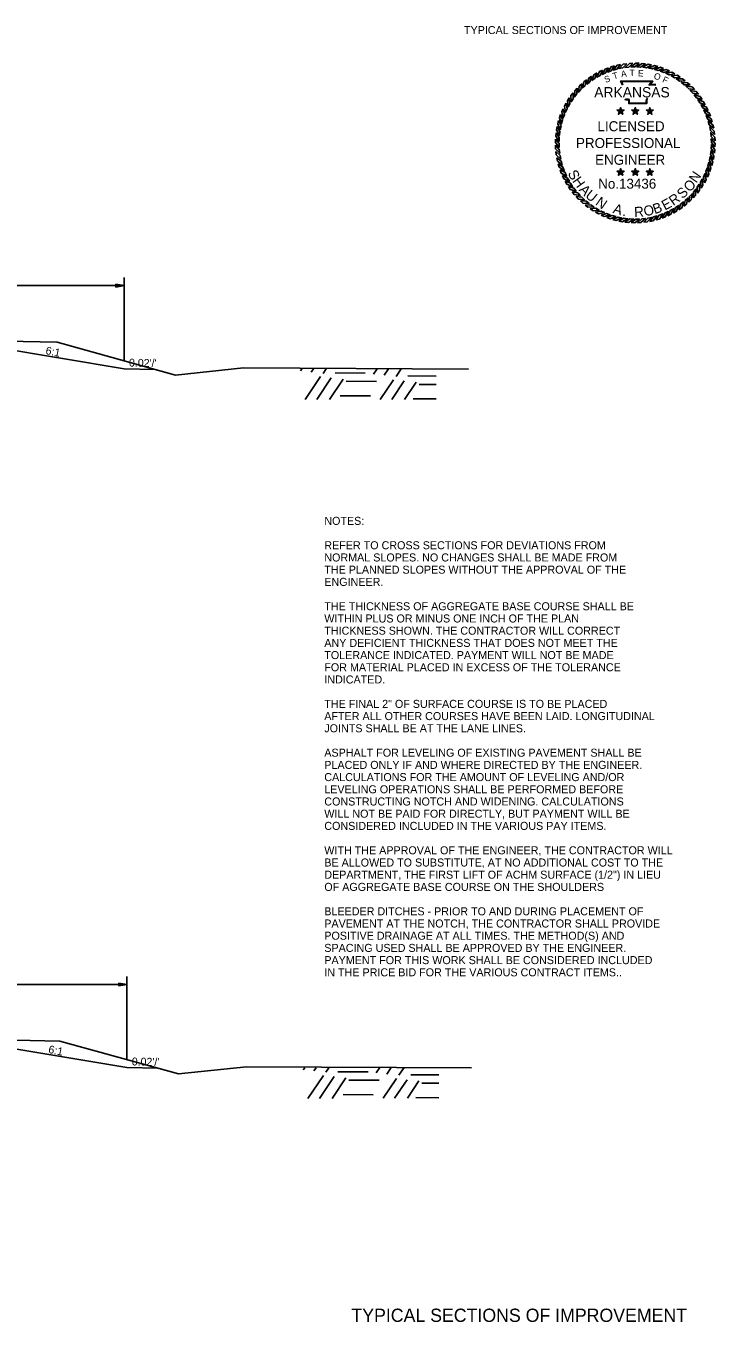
# Model space of a CAD drawing. Extents: x 1398565 to 1398920, y 1968324 to 1968581.
# Drawn here: x 1398668.3 to 1398719.8, y 1968325.3 to 1968422.2 of the extents above; entities that cross this region are included whole.
import ezdxf

# ---------------------------------------------------------------- set-up
doc = ezdxf.new("R2010")
doc.units = 0
for name, color, linetype in [('1', 7, 'Continuous'), ('10', 7, 'Continuous'), ('19', 7, 'Continuous'), ('42', 7, 'Continuous'), ('9', 7, 'Continuous'), ('G-ANNO-SYMB', 7, 'Continuous')]:
    doc.layers.add(name, color=color, linetype=linetype)

msp = doc.modelspace()

# ---------------------------------------------------------------- linework, layer by layer
at = {"layer": '19'}
for p, q in [((1398653.586, 1968402.763), (1398675.586, 1968402.763)), ((1398674.986, 1968402.658), (1398674.986, 1968402.868)), ((1398674.986, 1968402.868), (1398675.586, 1968402.763)), ((1398674.986, 1968402.813), (1398675.426, 1968402.778)), ((1398675.586, 1968402.763), (1398674.986, 1968402.658)), ((1398675.426, 1968402.748), (1398674.986, 1968402.708)), ((1398675.586, 1968397.155), (1398675.586, 1968403.363)), ((1398661.586, 1968398.88), (1398675.586, 1968396.547)), ((1398677.903, 1968396.501), (1398675.586, 1968396.547)), ((1398675.795, 1968344.892), (1398675.795, 1968351.1)), ((1398653.795, 1968350.5), (1398675.795, 1968350.5)), ((1398675.195, 1968350.395), (1398675.195, 1968350.605)), ((1398675.195, 1968350.605), (1398675.795, 1968350.5)), ((1398675.195, 1968350.55), (1398675.635, 1968350.515)), ((1398675.795, 1968350.5), (1398675.195, 1968350.395)), ((1398675.635, 1968350.485), (1398675.195, 1968350.445)), ((1398661.795, 1968346.618), (1398675.795, 1968344.284)), ((1398678.111, 1968344.238), (1398675.795, 1968344.284))]:
    msp.add_line(p, q, dxfattribs=at)
at = {"layer": '42'}
for points in [[(1398653.586, 1968398.994), (1398661.671, 1968398.71), (1398670.586, 1968398.534), (1398679.441, 1968396.073), (1398684.522, 1968396.615), (1398701.339, 1968396.526)], [(1398653.795, 1968346.731), (1398661.88, 1968346.447), (1398670.795, 1968346.271), (1398679.65, 1968343.81), (1398684.731, 1968344.352), (1398701.547, 1968344.263)]]:
    msp.add_lwpolyline(points, dxfattribs=at)
at = {"layer": '9'}
for p, q in [((1398688.776, 1968396.383), (1398688.88, 1968396.537)), ((1398689.125, 1968394.243), (1398690.279, 1968395.959)), ((1398689.574, 1968396.291), (1398689.74, 1968396.538)), ((1398689.985, 1968394.244), (1398691.076, 1968395.867)), ((1398690.464, 1968396.2), (1398690.692, 1968396.54)), ((1398690.938, 1968394.246), (1398691.966, 1968395.776)), ((1398691.354, 1968396.239), (1398693.615, 1968396.224)), ((1398694.227, 1968396.151), (1398694.493, 1968396.547)), ((1398694.739, 1968394.253), (1398695.73, 1968395.727)), ((1398695.025, 1968396.06), (1398695.353, 1968396.548)), ((1398695.915, 1968395.969), (1398696.306, 1968396.55)), ((1398696.805, 1968396.007), (1398698.911, 1968395.994)), ((1398692.189, 1968395.61), (1398694.451, 1968395.595)), ((1398695.599, 1968394.254), (1398696.527, 1968395.636)), ((1398696.551, 1968394.256), (1398697.417, 1968395.545)), ((1398697.64, 1968395.378), (1398698.912, 1968395.37)), ((1398691.746, 1968394.533), (1398694.008, 1968394.519)), ((1398697.197, 1968394.301), (1398698.914, 1968394.29)), ((1398688.985, 1968344.12), (1398689.089, 1968344.274)), ((1398689.334, 1968341.98), (1398690.488, 1968343.696)), ((1398689.782, 1968344.029), (1398689.948, 1968344.276)), ((1398690.194, 1968341.982), (1398691.285, 1968343.605)), ((1398690.673, 1968343.937), (1398690.901, 1968344.277)), ((1398691.146, 1968341.983), (1398692.175, 1968343.513)), ((1398691.562, 1968343.976), (1398693.824, 1968343.961)), ((1398692.398, 1968343.347), (1398694.66, 1968343.332)), ((1398694.436, 1968343.888), (1398694.702, 1968344.284)), ((1398694.948, 1968341.99), (1398695.939, 1968343.464)), ((1398695.234, 1968343.797), (1398695.562, 1968344.285)), ((1398695.807, 1968341.991), (1398696.736, 1968343.373)), ((1398696.124, 1968343.706), (1398696.514, 1968344.287)), ((1398697.014, 1968343.744), (1398699.119, 1968343.731)), ((1398696.76, 1968341.993), (1398697.626, 1968343.282)), ((1398697.849, 1968343.115), (1398699.121, 1968343.107)), ((1398691.955, 1968342.27), (1398694.217, 1968342.256)), ((1398697.406, 1968342.039), (1398699.122, 1968342.028))]:
    msp.add_line(p, q, dxfattribs=at)
at = {"layer": 'G-ANNO-SYMB'}
for points in [[(1398711.784, 1968419.05), (1398711.545, 1968418.958), (1398711.32, 1968418.56), (1398711.572, 1968418.674)], [(1398712.231, 1968419.19), (1398711.985, 1968419.117), (1398711.73, 1968418.738), (1398711.99, 1968418.832)], [(1398712.688, 1968419.294), (1398712.437, 1968419.241), (1398712.152, 1968418.883), (1398712.42, 1968418.957)], [(1398713.152, 1968419.362), (1398712.897, 1968419.329), (1398712.585, 1968418.995), (1398712.857, 1968419.047)], [(1398713.619, 1968419.394), (1398713.363, 1968419.381), (1398713.026, 1968419.072), (1398713.301, 1968419.103)], [(1398714.087, 1968419.389), (1398713.831, 1968419.396), (1398713.471, 1968419.115), (1398713.748, 1968419.124)], [(1398714.554, 1968419.347), (1398714.299, 1968419.375), (1398713.917, 1968419.122), (1398714.194, 1968419.109)], [(1398715.016, 1968419.269), (1398714.764, 1968419.316), (1398714.364, 1968419.095), (1398714.639, 1968419.06)], [(1398715.47, 1968419.155), (1398715.222, 1968419.222), (1398714.806, 1968419.032), (1398715.078, 1968418.976)], [(1398715.914, 1968419.005), (1398715.672, 1968419.092), (1398715.243, 1968418.935), (1398715.509, 1968418.858)], [(1398710.146, 1968418.155), (1398709.946, 1968417.994), (1398709.855, 1968417.546), (1398710.06, 1968417.732)], [(1398710.528, 1968418.426), (1398710.316, 1968418.281), (1398710.19, 1968417.842), (1398710.409, 1968418.012)], [(1398710.93, 1968418.667), (1398710.708, 1968418.539), (1398710.547, 1968418.111), (1398710.779, 1968418.263)], [(1398711.35, 1968418.875), (1398711.118, 1968418.765), (1398710.925, 1968418.351), (1398711.168, 1968418.484)], [(1398716.345, 1968418.822), (1398716.111, 1968418.926), (1398715.67, 1968418.804), (1398715.929, 1968418.706)], [(1398716.76, 1968418.604), (1398716.535, 1968418.727), (1398716.086, 1968418.64), (1398716.337, 1968418.522)], [(1398717.157, 1968418.355), (1398716.942, 1968418.496), (1398716.488, 1968418.444), (1398716.728, 1968418.307)], [(1398717.533, 1968418.076), (1398717.33, 1968418.233), (1398716.873, 1968418.217), (1398717.102, 1968418.061)], [(1398709.144, 1968417.174), (1398708.987, 1968416.971), (1398709.003, 1968416.514), (1398709.159, 1968416.743)], [(1398709.452, 1968417.527), (1398709.28, 1968417.337), (1398709.26, 1968416.88), (1398709.433, 1968417.096)], [(1398709.787, 1968417.855), (1398709.6, 1968417.678), (1398709.545, 1968417.224), (1398709.734, 1968417.427)], [(1398717.886, 1968417.768), (1398717.695, 1968417.94), (1398717.239, 1968417.96), (1398717.455, 1968417.787)], [(1398718.213, 1968417.433), (1398718.037, 1968417.62), (1398717.583, 1968417.675), (1398717.785, 1968417.486)], [(1398718.514, 1968417.074), (1398718.353, 1968417.274), (1398717.905, 1968417.365), (1398718.091, 1968417.16)], [(1398718.785, 1968416.692), (1398718.64, 1968416.904), (1398718.201, 1968417.03), (1398718.371, 1968416.811)], [(1398708.616, 1968416.401), (1398708.493, 1968416.176), (1398708.58, 1968415.727), (1398708.698, 1968415.978)], [(1398708.865, 1968416.798), (1398708.724, 1968416.583), (1398708.776, 1968416.129), (1398708.913, 1968416.37)], [(1398712.698, 1968415.806), (1398712.76, 1968415.891), (1398712.698, 1968416.079), (1398712.637, 1968415.891)], [(1398713.789, 1968415.806), (1398713.851, 1968415.891), (1398713.789, 1968416.079), (1398713.728, 1968415.891)], [(1398714.88, 1968415.806), (1398714.942, 1968415.891), (1398714.88, 1968416.079), (1398714.819, 1968415.891)], [(1398719.026, 1968416.29), (1398718.898, 1968416.512), (1398718.469, 1968416.672), (1398718.622, 1968416.441)], [(1398719.234, 1968415.87), (1398719.124, 1968416.102), (1398718.709, 1968416.295), (1398718.843, 1968416.052)], [(1398708.065, 1968415.111), (1398707.998, 1968414.864), (1398708.188, 1968414.447), (1398708.244, 1968414.719)], [(1398708.215, 1968415.555), (1398708.128, 1968415.314), (1398708.285, 1968414.884), (1398708.362, 1968415.15)], [(1398708.398, 1968415.986), (1398708.294, 1968415.752), (1398708.416, 1968415.311), (1398708.514, 1968415.571)], [(1398712.698, 1968415.806), (1398712.637, 1968415.891), (1398712.439, 1968415.891), (1398712.599, 1968415.774)], [(1398712.698, 1968415.806), (1398712.599, 1968415.774), (1398712.538, 1968415.586), (1398712.698, 1968415.702)], [(1398712.698, 1968415.806), (1398712.798, 1968415.774), (1398712.958, 1968415.891), (1398712.76, 1968415.891)], [(1398712.698, 1968415.806), (1398712.698, 1968415.702), (1398712.859, 1968415.586), (1398712.798, 1968415.774)], [(1398713.789, 1968415.806), (1398713.728, 1968415.891), (1398713.53, 1968415.891), (1398713.69, 1968415.774)], [(1398713.789, 1968415.806), (1398713.69, 1968415.774), (1398713.629, 1968415.586), (1398713.789, 1968415.702)], [(1398713.789, 1968415.806), (1398713.888, 1968415.774), (1398714.049, 1968415.891), (1398713.851, 1968415.891)], [(1398713.789, 1968415.806), (1398713.789, 1968415.702), (1398713.95, 1968415.586), (1398713.888, 1968415.774)], [(1398714.88, 1968415.806), (1398714.819, 1968415.891), (1398714.621, 1968415.891), (1398714.781, 1968415.774)], [(1398714.88, 1968415.806), (1398714.781, 1968415.774), (1398714.72, 1968415.586), (1398714.88, 1968415.702)], [(1398714.88, 1968415.806), (1398714.979, 1968415.774), (1398715.14, 1968415.891), (1398714.942, 1968415.891)], [(1398714.88, 1968415.806), (1398714.88, 1968415.702), (1398715.041, 1968415.586), (1398714.979, 1968415.774)], [(1398719.408, 1968415.436), (1398719.317, 1968415.675), (1398718.919, 1968415.9), (1398719.033, 1968415.648)], [(1398719.548, 1968414.989), (1398719.476, 1968415.235), (1398719.097, 1968415.49), (1398719.191, 1968415.23)], [(1398707.873, 1968414.195), (1398707.845, 1968413.94), (1398708.098, 1968413.559), (1398708.111, 1968413.836)], [(1398707.951, 1968414.657), (1398707.904, 1968414.405), (1398708.125, 1968414.005), (1398708.16, 1968414.28)], [(1398719.653, 1968414.532), (1398719.6, 1968414.783), (1398719.242, 1968415.068), (1398719.315, 1968414.8)], [(1398719.721, 1968414.068), (1398719.688, 1968414.323), (1398719.354, 1968414.635), (1398719.406, 1968414.362)], [(1398719.753, 1968413.601), (1398719.74, 1968413.857), (1398719.431, 1968414.194), (1398719.462, 1968413.919)], [(1398707.831, 1968413.728), (1398707.824, 1968413.472), (1398708.105, 1968413.112), (1398708.096, 1968413.389)], [(1398707.826, 1968413.26), (1398707.839, 1968413.004), (1398708.148, 1968412.667), (1398708.117, 1968412.942)], [(1398719.706, 1968412.666), (1398719.734, 1968412.921), (1398719.481, 1968413.302), (1398719.468, 1968413.026)], [(1398719.748, 1968413.133), (1398719.755, 1968413.389), (1398719.474, 1968413.749), (1398719.482, 1968413.472)], [(1398707.858, 1968412.793), (1398707.891, 1968412.538), (1398708.225, 1968412.226), (1398708.173, 1968412.499)], [(1398707.926, 1968412.329), (1398707.979, 1968412.078), (1398708.337, 1968411.794), (1398708.263, 1968412.061)], [(1398719.514, 1968411.75), (1398719.581, 1968411.998), (1398719.391, 1968412.414), (1398719.335, 1968412.142)], [(1398719.628, 1968412.204), (1398719.675, 1968412.456), (1398719.454, 1968412.856), (1398719.419, 1968412.581)], [(1398708.03, 1968411.873), (1398708.103, 1968411.626), (1398708.482, 1968411.371), (1398708.388, 1968411.632)], [(1398708.17, 1968411.426), (1398708.262, 1968411.186), (1398708.66, 1968410.961), (1398708.546, 1968411.213)], [(1398712.698, 1968411.238), (1398712.637, 1968411.322), (1398712.439, 1968411.322), (1398712.599, 1968411.206)], [(1398712.698, 1968411.238), (1398712.599, 1968411.206), (1398712.538, 1968411.017), (1398712.698, 1968411.134)], [(1398712.698, 1968411.238), (1398712.76, 1968411.322), (1398712.698, 1968411.511), (1398712.637, 1968411.322)], [(1398712.698, 1968411.238), (1398712.798, 1968411.206), (1398712.958, 1968411.322), (1398712.76, 1968411.322)], [(1398712.698, 1968411.238), (1398712.698, 1968411.134), (1398712.859, 1968411.017), (1398712.798, 1968411.206)], [(1398713.789, 1968411.238), (1398713.728, 1968411.322), (1398713.53, 1968411.322), (1398713.69, 1968411.206)], [(1398713.789, 1968411.238), (1398713.69, 1968411.206), (1398713.629, 1968411.017), (1398713.789, 1968411.134)], [(1398713.789, 1968411.238), (1398713.851, 1968411.322), (1398713.789, 1968411.511), (1398713.728, 1968411.322)], [(1398713.789, 1968411.238), (1398713.888, 1968411.206), (1398714.049, 1968411.322), (1398713.851, 1968411.322)], [(1398713.789, 1968411.238), (1398713.789, 1968411.134), (1398713.95, 1968411.017), (1398713.888, 1968411.206)], [(1398714.88, 1968411.238), (1398714.819, 1968411.322), (1398714.621, 1968411.322), (1398714.781, 1968411.206)], [(1398714.88, 1968411.238), (1398714.781, 1968411.206), (1398714.72, 1968411.017), (1398714.88, 1968411.134)], [(1398714.88, 1968411.238), (1398714.942, 1968411.322), (1398714.88, 1968411.511), (1398714.819, 1968411.322)], [(1398714.88, 1968411.238), (1398714.979, 1968411.206), (1398715.14, 1968411.322), (1398714.942, 1968411.322)], [(1398714.88, 1968411.238), (1398714.88, 1968411.134), (1398715.041, 1968411.017), (1398714.979, 1968411.206)], [(1398719.18, 1968410.875), (1398719.285, 1968411.109), (1398719.163, 1968411.55), (1398719.065, 1968411.291)], [(1398719.364, 1968411.306), (1398719.45, 1968411.548), (1398719.294, 1968411.977), (1398719.217, 1968411.711)], [(1398708.345, 1968410.991), (1398708.455, 1968410.759), (1398708.869, 1968410.566), (1398708.736, 1968410.809)], [(1398708.553, 1968410.571), (1398708.681, 1968410.349), (1398709.109, 1968410.189), (1398708.957, 1968410.42)], [(1398718.435, 1968409.687), (1398718.591, 1968409.89), (1398718.576, 1968410.347), (1398718.42, 1968410.118)], [(1398718.714, 1968410.063), (1398718.854, 1968410.278), (1398718.803, 1968410.732), (1398718.665, 1968410.492)], [(1398718.963, 1968410.46), (1398719.086, 1968410.685), (1398718.999, 1968411.134), (1398718.881, 1968410.883)], [(1398708.794, 1968410.169), (1398708.939, 1968409.958), (1398709.378, 1968409.831), (1398709.208, 1968410.05)], [(1398709.065, 1968409.787), (1398709.226, 1968409.588), (1398709.674, 1968409.496), (1398709.488, 1968409.701)], [(1398709.365, 1968409.428), (1398709.542, 1968409.241), (1398709.995, 1968409.186), (1398709.793, 1968409.375)], [(1398717.433, 1968408.706), (1398717.632, 1968408.867), (1398717.724, 1968409.315), (1398717.519, 1968409.129)], [(1398717.792, 1968409.007), (1398717.979, 1968409.183), (1398718.034, 1968409.637), (1398717.845, 1968409.435)], [(1398718.127, 1968409.334), (1398718.299, 1968409.525), (1398718.319, 1968409.981), (1398718.146, 1968409.765)], [(1398709.693, 1968409.093), (1398709.883, 1968408.921), (1398710.34, 1968408.901), (1398710.124, 1968409.074)], [(1398710.046, 1968408.785), (1398710.249, 1968408.629), (1398710.706, 1968408.644), (1398710.477, 1968408.8)], [(1398710.422, 1968408.506), (1398710.637, 1968408.366), (1398711.091, 1968408.417), (1398710.85, 1968408.555)], [(1398710.819, 1968408.257), (1398711.044, 1968408.134), (1398711.493, 1968408.221), (1398711.242, 1968408.339)], [(1398715.794, 1968407.812), (1398716.034, 1968407.903), (1398716.259, 1968408.301), (1398716.007, 1968408.187)], [(1398716.229, 1968407.986), (1398716.461, 1968408.096), (1398716.654, 1968408.511), (1398716.411, 1968408.377)], [(1398716.649, 1968408.194), (1398716.871, 1968408.322), (1398717.031, 1968408.751), (1398716.8, 1968408.598)], [(1398717.051, 1968408.435), (1398717.262, 1968408.58), (1398717.389, 1968409.019), (1398717.17, 1968408.849)], [(1398711.234, 1968408.04), (1398711.468, 1968407.935), (1398711.909, 1968408.057), (1398711.649, 1968408.155)], [(1398711.665, 1968407.856), (1398711.906, 1968407.77), (1398712.336, 1968407.926), (1398712.07, 1968408.003)], [(1398712.109, 1968407.706), (1398712.356, 1968407.639), (1398712.772, 1968407.829), (1398712.501, 1968407.885)], [(1398712.563, 1968407.592), (1398712.815, 1968407.545), (1398713.215, 1968407.766), (1398712.94, 1968407.801)], [(1398713.025, 1968407.514), (1398713.28, 1968407.486), (1398713.661, 1968407.739), (1398713.384, 1968407.752)], [(1398713.491, 1968407.472), (1398713.748, 1968407.465), (1398714.108, 1968407.746), (1398713.831, 1968407.738)], [(1398713.96, 1968407.467), (1398714.216, 1968407.48), (1398714.553, 1968407.789), (1398714.278, 1968407.758)], [(1398714.427, 1968407.499), (1398714.682, 1968407.532), (1398714.994, 1968407.866), (1398714.721, 1968407.814)], [(1398714.891, 1968407.567), (1398715.142, 1968407.62), (1398715.426, 1968407.978), (1398715.159, 1968407.905)], [(1398715.347, 1968407.672), (1398715.594, 1968407.744), (1398715.849, 1968408.123), (1398715.588, 1968408.029)]]:
    msp.add_lwpolyline(points, close=True, dxfattribs=at)
for points in [[(1398712.834, 1968417.761), (1398712.695, 1968418.062), (1398715.101, 1968418.063), (1398714.9, 1968417.811), (1398715.063, 1968417.813), (1398715.2, 1968417.814), (1398715.336, 1968417.8)], [(1398712.868, 1968417.777), (1398712.754, 1968418.024), (1398715.022, 1968418.025), (1398714.82, 1968417.771), (1398715.064, 1968417.775), (1398715.198, 1968417.776), (1398715.332, 1968417.762)], [(1398714.722, 1968416.752), (1398714.681, 1968416.719), (1398714.667, 1968416.669), (1398714.653, 1968416.544), (1398714.653, 1968416.378), (1398713.31, 1968416.378), (1398713.31, 1968416.602), (1398713.31, 1968416.652), (1398713.256, 1968416.669), (1398713.065, 1968416.669), (1398713.031, 1968416.721)], [(1398714.698, 1968416.782), (1398714.647, 1968416.741), (1398714.629, 1968416.676), (1398714.615, 1968416.546), (1398714.615, 1968416.416), (1398713.348, 1968416.416), (1398713.348, 1968416.602), (1398713.348, 1968416.68), (1398713.261, 1968416.707), (1398713.085, 1968416.707), (1398713.062, 1968416.742)]]:
    msp.add_lwpolyline(points, dxfattribs=at)

# ---------------------------------------------------------------- texts
at = {"layer": '1'}
msp.add_text('TYPICAL SECTIONS OF IMPROVEMENT', height=0.6, dxfattribs=at).set_placement((1398700.991, 1968421.577))
at = {"layer": '10'}
for p in [(1398669.689, 1968397.644), (1398669.898, 1968345.381)]:
    msp.add_text('6:1', height=0.59, rotation=348.76163, dxfattribs=at).set_placement(p)
at = {"layer": '19'}
for p in [(1398675.954, 1968396.712), (1398676.163, 1968344.449)]:
    msp.add_text("0.02'/'", height=0.59, rotation=358.85424, dxfattribs=at).set_placement(p)
for s, height, p in [('NOTES:', 0.6, (1398690.554, 1968384.871)), ('REFER TO CROSS SECTIONS FOR DEVIATIONS FROM', 0.6, (1398690.554, 1968383.046)), ('NORMAL SLOPES. NO CHANGES SHALL BE MADE FROM ', 0.6, (1398690.554, 1968382.134)), ('THE PLANNED SLOPES WITHOUT THE APPROVAL OF THE', 0.6, (1398690.554, 1968381.221)), ('ENGINEER.', 0.6, (1398690.554, 1968380.309)), ('THE THICKNESS OF AGGREGATE BASE COURSE SHALL BE', 0.6, (1398690.554, 1968378.484)), ('WITHIN PLUS OR MINUS ONE INCH OF THE PLAN ', 0.6, (1398690.554, 1968377.571)), ('THICKNESS SHOWN. THE CONTRACTOR WILL CORRECT', 0.6, (1398690.554, 1968376.659)), ('ANY DEFICIENT THICKNESS THAT DOES NOT MEET THE', 0.6, (1398690.554, 1968375.746)), ('TOLERANCE INDICATED. PAYMENT WILL NOT BE MADE', 0.6, (1398690.554, 1968374.834)), ('FOR MATERIAL PLACED IN EXCESS OF THE TOLERANCE', 0.6, (1398690.554, 1968373.921)), ('INDICATED.', 0.6, (1398690.554, 1968373.009)), ('THE FINAL 2" OF SURFACE COURSE IS TO BE PLACED', 0.6, (1398690.554, 1968371.184)), ('AFTER ALL OTHER COURSES HAVE BEEN LAID. LONGITUDINAL', 0.6, (1398690.554, 1968370.271)), ('JOINTS SHALL BE AT THE LANE LINES.', 0.6, (1398690.554, 1968369.359)), ('ASPHALT FOR LEVELING OF EXISTING PAVEMENT SHALL BE', 0.6, (1398690.554, 1968367.534)), ('PLACED ONLY IF AND WHERE DIRECTED BY THE ENGINEER.', 0.6, (1398690.554, 1968366.621)), ('CALCULATIONS FOR THE AMOUNT OF LEVELING AND/OR', 0.6, (1398690.554, 1968365.709)), ('LEVELING OPERATIONS SHALL BE PERFORMED BEFORE ', 0.6, (1398690.554, 1968364.796)), ('CONSTRUCTING NOTCH AND WIDENING. CALCULATIONS', 0.6, (1398690.554, 1968363.884)), ('WILL NOT BE PAID FOR DIRECTLY, BUT PAYMENT WILL BE', 0.6, (1398690.554, 1968362.971)), ('CONSIDERED INCLUDED IN THE VARIOUS PAY ITEMS.', 0.6, (1398690.554, 1968362.059)), ('WITH THE APPROVAL OF THE ENGINEER, THE CONTRACTOR WILL', 0.6, (1398690.554, 1968360.234)), ('BE ALLOWED TO SUBSTITUTE, AT NO ADDITIONAL COST TO THE', 0.6, (1398690.554, 1968359.321)), ('DEPARTMENT, THE FIRST LIFT OF ACHM SURFACE (1/2") IN LIEU', 0.6, (1398690.554, 1968358.409)), ('OF AGGREGATE BASE COURSE ON THE SHOULDERS', 0.6, (1398690.554, 1968357.496)), ('BLEEDER DITCHES - PRIOR TO AND DURING PLACEMENT OF', 0.6, (1398690.554, 1968355.671)), ('PAVEMENT AT THE NOTCH, THE CONTRACTOR SHALL PROVIDE', 0.6, (1398690.554, 1968354.759)), ('POSITIVE DRAINAGE AT ALL TIMES. THE METHOD(S) AND', 0.6, (1398690.554, 1968353.846)), ('SPACING USED SHALL BE APPROVED BY THE ENGINEER.', 0.6, (1398690.554, 1968352.934)), ('PAYMENT FOR THIS WORK SHALL BE CONSIDERED INCLUDED', 0.6, (1398690.554, 1968352.021)), ('IN THE PRICE BID FOR THE VARIOUS CONTRACT ITEMS..', 0.6, (1398690.554, 1968351.109)), ('TYPICAL SECTIONS OF IMPROVEMENT', 0.98999, (1398692.58, 1968325.265))]:
    msp.add_text(s, height=height, dxfattribs=at).set_placement(p)
at = {"layer": 'G-ANNO-SYMB'}
for s, height, rotation, p in [('S', 0.475, 19.77256, (1398711.58, 1968417.918)), ('T', 0.475, 16.90148, (1398712.184, 1968418.189)), ('A', 0.475, 8.67877, (1398712.76, 1968418.34)), ('T', 0.475, 1.47887, (1398713.373, 1968418.434)), ('E', 0.475, 356.67203, (1398713.981, 1968418.42)), ('O', 0.475, 341.2218, (1398715.133, 1968418.257)), ('F', 0.475, 335.36282, (1398715.773, 1968418.007)), ('ARKANSAS', 0.7747, 360, (1398710.727, 1968416.839)), ('LICENSED', 0.75, 360, (1398710.968, 1968414.31)), ('PROFESSIONAL', 0.75, 360, (1398709.361, 1968413.056)), ('ENGINEER', 0.75, 360, (1398710.789, 1968411.801)), ('S', 0.75, 298.16364, (1398708.721, 1968411.171)), ('N', 0.75, 56.10067, (1398718.363, 1968410.387)), ('H', 0.75, 305.61905, (1398709.063, 1968410.583)), ('No.13436', 0.747, 360, (1398711.026, 1968410.013)), ('O', 0.75, 44.77573, (1398717.843, 1968409.712)), ('A', 0.75, 313.44722, (1398709.54, 1968409.898)), ('U', 0.75, 320.90262, (1398710.007, 1968409.409)), ('N', 0.75, 324.93262, (1398710.763, 1968408.851)), ('E', 0.75, 27.83149, (1398716.004, 1968408.373)), ('R', 0.75, 35.65967, (1398716.638, 1968408.705)), ('S', 0.75, 43.48784, (1398717.327, 1968409.214)), ('A', 0.75, 343.09908, (1398712.07, 1968408.207)), ('R', 0.75, 3.22866, (1398713.727, 1968407.894)), ('O', 0.75, 11.42961, (1398714.494, 1968407.942)), ('B', 0.75, 18.88501, (1398715.246, 1968408.102)), ('.', 0.75, 351.30002, (1398712.807, 1968407.989))]:
    msp.add_text(s, height=height, rotation=rotation, dxfattribs=at).set_placement(p)

doc.saveas('drawing.dxf')
